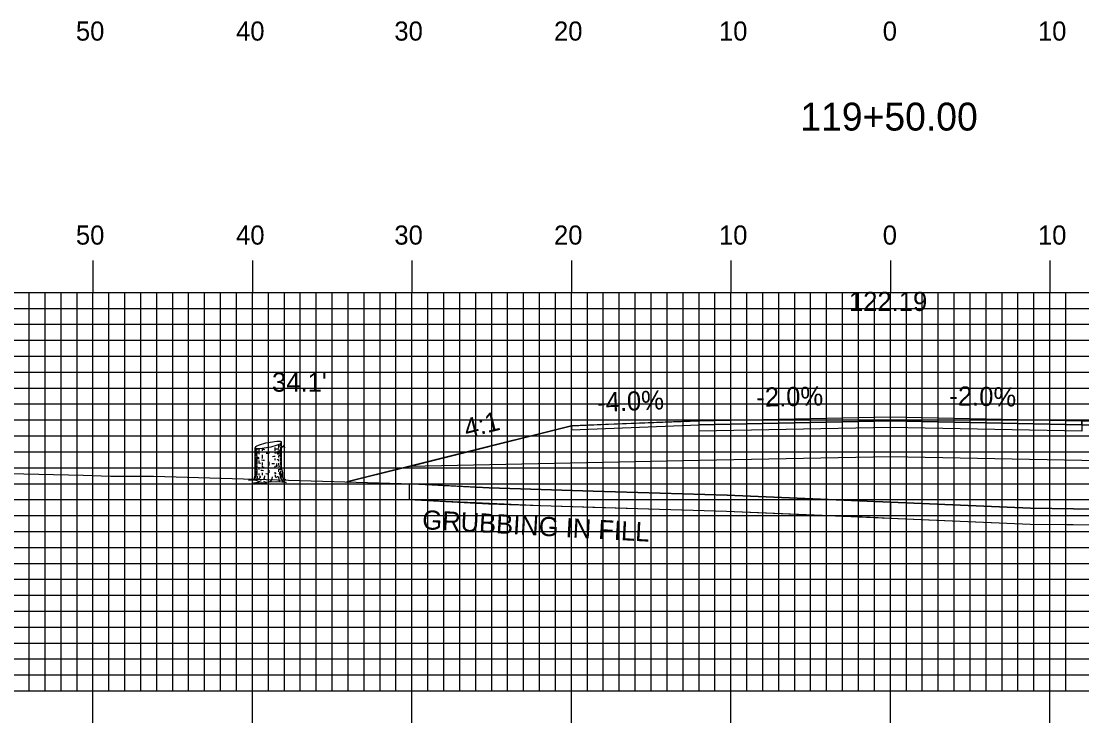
# Model space of a CAD drawing. Extents: x 1771629 to 1771972, y 442591 to 442811.
# Drawn here: x 1771740.1 to 1771806.6, y 442696.7 to 442740.7 of the extents above; entities that cross this region are included whole.
import ezdxf

# ---------------------------------------------------------------- set-up
doc = ezdxf.new("R2010")
doc.units = 0
for name, color, linetype in [('ANNOTATION', 7, 'Continuous'), ('D_Roadway_Centerline', 7, 'Continuous'), ('D_Roadway_Centerline_Text', 7, 'Continuous'), ('D_Roadway_Edge_Shoulder', 7, 'Continuous'), ('D_Roadway_Edge_TW', 7, 'Continuous'), ('D_Roadway_Pavement', 7, 'Continuous'), ('D_Roadway_SlopeLines', 7, 'Continuous'), ('D_Roadway_SubGrade', 7, 'Continuous'), ('D_Text_Standard', 7, 'Continuous'), ('GRUBBING IN FILL', 7, 'Continuous'), ('H_V ANNOTATION', 7, 'Continuous'), ('M_Trees_Conifer_Pay', 7, 'Continuous'), ('MAJOR', 7, 'Continuous'), ('MINOR', 7, 'Continuous'), ('S_Roadway_Centerline', 7, 'Continuous')]:
    doc.layers.add(name, color=color, linetype=linetype)

msp = doc.modelspace()

# ---------------------------------------------------------------- linework, layer by layer
at = {"layer": 'D_Roadway_Centerline'}
msp.add_lwpolyline([(1771760.497, 442711.776), (1771764.04, 442712.662), (1771764.407, 442712.753), (1771767.076, 442713.421), (1771774.552, 442715.29), (1771774.581, 442715.297), (1771776.908, 442715.39), (1771782.58, 442715.617), (1771794.576, 442715.857), (1771794.581, 442715.857), (1771806.579, 442715.617), (1771806.58, 442715.617), (1771809.705, 442715.492), (1771814.547, 442715.299), (1771814.58, 442715.297), (1771824.673, 442712.774), (1771824.754, 442712.753), (1771824.845, 442712.731), (1771834.313, 442710.363), (1771835.958, 442709.952)], dxfattribs=at)
at = {"layer": 'D_Roadway_Edge_Shoulder'}
for points in [[(1771782.58, 442715.617), (1771774.581, 442715.297), (1771774.581, 442715.047), (1771782.58, 442715.367)], [(1771806.58, 442715.617), (1771814.58, 442715.297), (1771814.58, 442715.047), (1771806.58, 442715.367)]]:
    msp.add_lwpolyline(points, close=True, dxfattribs=at)
at = {"layer": 'D_Roadway_Edge_TW'}
msp.add_lwpolyline([(1771782.58, 442715.367), (1771782.58, 442715.617), (1771794.581, 442715.857), (1771806.58, 442715.617), (1771806.58, 442715.367), (1771794.581, 442715.607)], close=True, dxfattribs=at)
at = {"layer": 'D_Roadway_Pavement'}
msp.add_lwpolyline([(1771782.58, 442714.95), (1771782.58, 442715.367), (1771794.581, 442715.607), (1771806.58, 442715.367), (1771806.58, 442714.95), (1771794.581, 442715.19)], close=True, dxfattribs=at)
at = {"layer": 'D_Roadway_SlopeLines'}
msp.add_lwpolyline([(1771774.581, 442715.297), (1771760.497, 442711.776)], dxfattribs=at)
at = {"layer": 'D_Roadway_SubGrade'}
msp.add_lwpolyline([(1771782.58, 442713.117), (1771764.406, 442712.753), (1771774.581, 442715.297), (1771774.581, 442715.047), (1771782.58, 442715.367), (1771794.581, 442715.607), (1771806.58, 442715.367), (1771814.58, 442715.047), (1771814.58, 442715.297), (1771824.754, 442712.753), (1771806.58, 442713.117), (1771794.581, 442713.357)], close=True, dxfattribs=at)
at = {"layer": 'GRUBBING IN FILL'}
msp.add_line((1771764.406, 442711.66), (1771764.406, 442710.663), dxfattribs=at)
msp.add_line((1771764.406, 442711.66), (1771764.406, 442710.663), dxfattribs=at)
for points in [[(1771764.406, 442710.663), (1771772.65, 442710.296), (1771780.107, 442710.064), (1771784.299, 442709.937), (1771793.82, 442709.534), (1771794.58, 442709.502), (1771794.58, 442710.503), (1771784.335, 442710.937), (1771775.947, 442711.189), (1771772.686, 442711.295), (1771769.426, 442711.401), (1771764.406, 442711.66)], [(1771764.406, 442710.663), (1771772.65, 442710.296), (1771780.107, 442710.064), (1771784.299, 442709.937), (1771793.82, 442709.534), (1771794.58, 442709.502), (1771794.58, 442710.503), (1771784.335, 442710.937), (1771775.947, 442711.189), (1771772.686, 442711.295), (1771769.426, 442711.401), (1771764.406, 442711.66)], [(1771794.58, 442709.502), (1771803.34, 442709.131), (1771810.221, 442709.056), (1771814.394, 442709.016), (1771819.574, 442708.992), (1771824.754, 442708.968), (1771824.754, 442709.968), (1771820.08, 442709.99), (1771814.401, 442710.016), (1771806.06, 442710.097), (1771803.368, 442710.131), (1771794.58, 442710.503)], [(1771794.58, 442709.502), (1771803.34, 442709.131), (1771810.221, 442709.056), (1771814.394, 442709.016), (1771819.574, 442708.992), (1771824.754, 442708.968), (1771824.754, 442709.968), (1771820.08, 442709.99), (1771814.401, 442710.016), (1771806.06, 442710.097), (1771803.368, 442710.131), (1771794.58, 442710.503)]]:
    msp.add_lwpolyline(points, close=True, dxfattribs=at)
msp.add_lwpolyline([(1771764.406, 442710.663), (1771769.384, 442710.401), (1771775.916, 442710.19), (1771784.299, 442709.937), (1771803.34, 442709.131), (1771806.049, 442709.097), (1771814.394, 442709.016), (1771824.754, 442708.968)], dxfattribs=at)
msp.add_lwpolyline([(1771764.406, 442710.663), (1771769.384, 442710.401), (1771775.916, 442710.19), (1771784.299, 442709.937), (1771803.34, 442709.131), (1771806.049, 442709.097), (1771814.394, 442709.016), (1771824.754, 442708.968)], dxfattribs=at)
at = {"layer": 'M_Trees_Conifer_Pay'}
for p, q in [((1771756.335, 442714.187), (1771756.335, 442714.025)), ((1771756.407, 442712.612), (1771756.407, 442714.259)), ((1771754.743, 442712.202), (1771754.743, 442713.924)), ((1771754.79, 442713.887), (1771754.79, 442713.416)), ((1771754.848, 442713.876), (1771754.848, 442713.778)), ((1771754.848, 442713.704), (1771754.848, 442713.5)), ((1771754.974, 442713.868), (1771754.974, 442713.635)), ((1771754.974, 442713.595), (1771754.974, 442713.521)), ((1771755.194, 442713.888), (1771755.194, 442713.72)), ((1771755.599, 442713.656), (1771755.599, 442713.561)), ((1771755.99, 442713.93), (1771755.99, 442713.731)), ((1771755.99, 442713.673), (1771755.99, 442713.584)), ((1771756.218, 442714.126), (1771756.218, 442713.903)), ((1771756.218, 442713.815), (1771756.218, 442713.767)), ((1771756.275, 442713.631), (1771756.224, 442713.572)), ((1771756.335, 442713.957), (1771756.335, 442713.829)), ((1771756.335, 442713.642), (1771756.335, 442713.306)), ((1771754.79, 442713.351), (1771754.79, 442713.043)), ((1771754.79, 442712.996), (1771754.79, 442712.504)), ((1771754.848, 442713.442), (1771754.848, 442713.242)), ((1771754.848, 442713.195), (1771754.848, 442712.859)), ((1771754.974, 442713.117), (1771754.974, 442712.979)), ((1771755.194, 442713.483), (1771755.194, 442713.246)), ((1771755.194, 442713.002), (1771755.194, 442712.849)), ((1771755.599, 442713.043), (1771755.599, 442712.969)), ((1771755.599, 442712.944), (1771755.599, 442712.796)), ((1771755.99, 442713.236), (1771755.99, 442713.131)), ((1771756.218, 442713.432), (1771756.218, 442713.3)), ((1771756.218, 442713.189), (1771756.218, 442713.08)), ((1771756.218, 442712.944), (1771756.218, 442712.802)), ((1771756.335, 442713.269), (1771756.335, 442713.107)), ((1771756.335, 442713.059), (1771756.335, 442712.843)), ((1771754.79, 442712.45), (1771754.79, 442712.202)), ((1771754.848, 442712.806), (1771754.848, 442712.67)), ((1771754.848, 442712.571), (1771754.848, 442712.193)), ((1771754.974, 442712.707), (1771754.974, 442712.565)), ((1771754.974, 442712.303), (1771754.974, 442712.209)), ((1771755.194, 442712.806), (1771755.194, 442712.633)), ((1771755.194, 442712.355), (1771755.194, 442712.202)), ((1771755.599, 442712.504), (1771755.599, 442712.351)), ((1771755.99, 442712.765), (1771755.99, 442712.618)), ((1771755.99, 442712.386), (1771755.99, 442712.298)), ((1771756.218, 442712.575), (1771756.218, 442712.402)), ((1771756.335, 442712.812), (1771756.335, 442712.738)), ((1771756.335, 442712.697), (1771756.335, 442712.524)), ((1771754.974, 442711.809), (1771755.137, 442711.873)), ((1771755.411, 442711.745), (1771755.285, 442711.809))]:
    msp.add_line(p, q, dxfattribs=at)
for points in [[(1771756.19, 442713.72), (1771756.159, 442713.635), (1771756.156, 442713.568), (1771756.186, 442713.504)], [(1771756.224, 442713.757), (1771756.261, 442713.683), (1771756.308, 442713.74), (1771756.366, 442713.809), (1771756.458, 442714.002), (1771756.522, 442714.049), (1771756.553, 442714.056)], [(1771756.238, 442713.504), (1771756.275, 442713.631), (1771756.339, 442713.747), (1771756.369, 442713.815), (1771756.438, 442713.961)], [(1771756.453, 442713.99), (1771756.528, 442713.998), (1771756.6, 442713.899)], [(1771754.922, 442713.23), (1771754.916, 442713.325), (1771754.959, 442713.302), (1771754.959, 442713.208)], [(1771756.061, 442712.831), (1771756.074, 442712.754), (1771756.121, 442712.765), (1771756.108, 442712.931)], [(1771756.407, 442712.612), (1771756.458, 442712.351), (1771756.474, 442712.077), (1771756.532, 442711.952), (1771756.668, 442711.921), (1771756.438, 442711.883), (1771756.438, 442711.883), (1771756.444, 442711.836), (1771756.691, 442711.742), (1771756.417, 442711.758), (1771756.061, 442711.778), (1771755.74, 442711.768), (1771755.746, 442711.851), (1771755.598, 442711.768), (1771755.411, 442711.745), (1771755.435, 442711.677), (1771755.167, 442711.721), (1771754.947, 442711.694), (1771754.654, 442711.711), (1771754.943, 442711.768), (1771754.974, 442711.809), (1771754.811, 442711.867), (1771754.574, 442711.878), (1771754.333, 442711.878), (1771754.675, 442711.935), (1771754.717, 442712.015), (1771754.743, 442712.202)], [(1771755.997, 442712.219), (1771756.007, 442712.093), (1771756.081, 442712.05)], [(1771756.234, 442712.324), (1771756.308, 442712.219), (1771756.312, 442712.046), (1771756.438, 442711.883)], [(1771756.333, 442712.47), (1771756.339, 442712.324), (1771756.386, 442712.256), (1771756.396, 442712.057)], [(1771754.791, 442712.155), (1771754.77, 442712.077), (1771754.749, 442711.983)], [(1771754.869, 442712.135), (1771754.875, 442712.019), (1771754.822, 442711.931), (1771754.811, 442711.867)], [(1771755.032, 442712.162), (1771755.032, 442712.03), (1771754.943, 442711.931)], [(1771755.258, 442711.921), (1771755.325, 442712.015), (1771755.352, 442712.155)], [(1771755.746, 442711.851), (1771755.82, 442711.992), (1771755.83, 442712.093)], [(1771756.275, 442711.83), (1771756.261, 442711.968), (1771756.186, 442712.097)]]:
    msp.add_lwpolyline(points, dxfattribs=at)
for centre, radius, start, end in [((1771756.599, 442709.157), 5.179, 101.7194, 108.05939), ((1771756.599, 442709.157), 5.179, 95.37941, 101.7194), ((1771756.188, 442713.515), 0.802, 79.2194, 95.37941), ((1771755.908, 442714.865), 0.802, 288.05939, 304.2194), ((1771756.291, 442714.056), 0.251, 71.05013, 79.2194), ((1771756.218, 442714.41), 0.251, 304.2194, 312.38868), ((1771756.346, 442714.216), 0.0817, 56.7194, 71.05013), ((1771756.332, 442714.285), 0.0817, 312.38868, 326.7194), ((1771756.362, 442714.24), 0.0527, 46.92298, 56.7194), ((1771756.377, 442714.255), 0.0314, 34.2194, 46.92298), ((1771756.356, 442714.269), 0.0527, 326.7194, 336.51582), ((1771756.381, 442714.258), 0.0264, 23.40735, 34.2194), ((1771756.376, 442714.261), 0.0314, 336.51582, 349.2194), ((1771756.384, 442714.26), 0.0226, 11.7194, 23.40735), ((1771756.384, 442714.26), 0.0226, 0.03145, 11.7194), ((1771756.381, 442714.26), 0.0264, 349.2194, 0.03145), ((1771754.775, 442713.746), 0.0334, 163.94846, 180), ((1771754.775, 442713.746), 0.0334, 180, 196.05154), ((1771754.774, 442713.923), 0.0314, 156.51582, 169.2194), ((1771754.769, 442713.924), 0.0264, 169.2194, 180.03145), ((1771754.766, 442713.924), 0.0226, 180.03145, 191.7194), ((1771754.766, 442713.924), 0.0226, 191.7194, 203.40735), ((1771754.785, 442713.749), 0.0441, 196.05154, 210), ((1771754.794, 442713.914), 0.0527, 146.7194, 156.51582), ((1771754.769, 442713.925), 0.0264, 203.40735, 214.2194), ((1771754.773, 442713.928), 0.0314, 214.2194, 226.92298), ((1771754.801, 442713.758), 0.0624, 210, 228.74941), ((1771754.818, 442713.899), 0.0817, 132.38868, 146.7194), ((1771754.788, 442713.944), 0.0527, 226.92298, 236.7194), ((1771754.804, 442713.968), 0.0817, 236.7194, 251.05013), ((1771754.874, 442713.841), 0.172, 228.74941, 240), ((1771754.932, 442713.774), 0.251, 124.2194, 132.38868), ((1771754.858, 442714.128), 0.251, 251.05013, 259.2194), ((1771755.073, 442714.186), 0.571, 240, 240.33672), ((1771755.242, 442713.318), 0.802, 108.05939, 124.2194), ((1771754.962, 442714.669), 0.802, 259.2194, 275.37941), ((1771755.073, 442714.186), 0.571, 246.85973, 257.98457), ((1771754.551, 442719.027), 5.179, 275.37941, 281.7194), ((1771755.575, 442717.936), 4.124, 264.6955, 266.73309), ((1771755.574, 442717.703), 4.124, 268.07512, 270), ((1771755.574, 442717.703), 4.124, 270, 270.35814), ((1771754.551, 442719.027), 5.179, 281.7194, 288.05939), ((1771755.574, 442717.703), 4.124, 275.78493, 277.05584), ((1771755.575, 442717.936), 4.124, 276.23804, 278.1032), ((1771756.076, 442714.419), 0.571, 278.1032, 284.36665), ((1771756.076, 442714.573), 0.571, 284.43166, 292.41325), ((1771756.076, 442714.419), 0.571, 297.0237, 300), ((1771756.275, 442714.228), 0.172, 300, 311.25059), ((1771756.275, 442714.073), 0.172, 300, 311.25059), ((1771756.348, 442714.145), 0.0624, 311.25059, 330), ((1771756.348, 442713.991), 0.0624, 311.25059, 330), ((1771756.363, 442714.136), 0.0441, 330, 343.94846), ((1771756.363, 442713.982), 0.0441, 330, 343.94846), ((1771756.374, 442714.133), 0.0334, 343.94846, 354.21506), ((1771756.374, 442713.979), 0.0334, 343.94846, 354.21506), ((1771756.374, 442713.535), 0.0334, 343.94846, 354.21506), ((1771754.775, 442713.299), 0.0334, 163.94846, 180), ((1771754.775, 442713.299), 0.0334, 180, 196.05154), ((1771754.775, 442713.089), 0.0334, 163.94846, 180), ((1771754.775, 442713.089), 0.0334, 180, 196.05154), ((1771754.775, 442712.852), 0.0334, 163.94846, 180), ((1771754.775, 442712.852), 0.0334, 180, 196.05154), ((1771754.785, 442713.302), 0.0441, 196.05154, 210), ((1771754.785, 442713.092), 0.0441, 196.05154, 210), ((1771754.801, 442713.311), 0.0624, 210, 228.74941), ((1771754.801, 442713.101), 0.0624, 210, 228.74941), ((1771754.874, 442713.394), 0.172, 228.74941, 240), ((1771754.874, 442713.184), 0.172, 228.74941, 240), ((1771755.073, 442713.739), 0.571, 240, 240.33672), ((1771755.073, 442713.529), 0.571, 240, 246.85973), ((1771755.074, 442713.975), 0.571, 240, 247.05866), ((1771755.073, 442713.529), 0.571, 259.27072, 261.8968), ((1771755.574, 442717.046), 4.124, 261.8968, 263.14738), ((1771755.574, 442717.256), 4.124, 264.08098, 266.66759), ((1771755.574, 442717.046), 4.124, 270, 270.35814), ((1771755.574, 442717.046), 4.124, 273.14934, 275.45691), ((1771755.575, 442717.492), 4.124, 273.70524, 275.95043), ((1771755.574, 442717.256), 4.124, 277.61247, 278.1032), ((1771756.074, 442713.739), 0.571, 278.1032, 286.92962), ((1771756.076, 442713.975), 0.571, 284.44928, 297.04285), ((1771756.074, 442713.739), 0.571, 297.18959, 300), ((1771756.074, 442713.529), 0.571, 297.18959, 300), ((1771756.274, 442713.394), 0.172, 300, 311.25059), ((1771756.274, 442713.184), 0.172, 300, 311.25059), ((1771756.346, 442713.311), 0.0624, 311.25059, 330), ((1771756.346, 442713.101), 0.0624, 311.25059, 330), ((1771756.362, 442713.302), 0.0441, 330, 343.94846), ((1771756.362, 442713.092), 0.0441, 330, 343.94846), ((1771756.372, 442713.299), 0.0334, 343.94846, 354.21506), ((1771756.372, 442713.089), 0.0334, 343.94846, 354.21506), ((1771754.775, 442712.655), 0.0334, 163.94846, 180), ((1771754.775, 442712.459), 0.0334, 163.94846, 180), ((1771754.775, 442712.459), 0.0334, 180, 196.05154), ((1771754.775, 442712.239), 0.0334, 163.94846, 180), ((1771754.775, 442712.239), 0.0334, 180, 196.05154), ((1771754.785, 442712.855), 0.0441, 196.05154, 210), ((1771754.785, 442712.462), 0.0441, 196.05154, 210), ((1771754.785, 442712.242), 0.0441, 196.05154, 210), ((1771754.801, 442712.864), 0.0624, 210, 228.74941), ((1771754.801, 442712.471), 0.0624, 210, 228.74941), ((1771754.801, 442712.251), 0.0624, 210, 228.74941), ((1771754.874, 442712.947), 0.172, 228.74941, 240), ((1771754.874, 442712.554), 0.172, 228.74941, 240), ((1771754.874, 442712.333), 0.172, 228.74941, 240), ((1771755.073, 442713.292), 0.571, 240, 246.85973), ((1771755.062, 442713.1), 0.571, 241.23686, 248.02677), ((1771755.073, 442712.899), 0.571, 240, 246.85973), ((1771755.073, 442712.678), 0.571, 240, 244.53138), ((1771755.574, 442716.612), 4.124, 263.49906, 265.83975), ((1771755.574, 442716.81), 4.124, 264.71603, 266.31934), ((1771755.574, 442716.416), 4.124, 267.81166, 270), ((1771755.574, 442716.416), 4.124, 270, 270.13279), ((1771755.574, 442716.416), 4.124, 275.78493, 276.78961), ((1771756.074, 442713.292), 0.571, 285.39827, 297.18959), ((1771756.074, 442712.899), 0.571, 288.50673, 297.27208), ((1771756.074, 442713.094), 0.571, 289.29072, 300), ((1771756.274, 442712.749), 0.172, 300, 311.25059), ((1771756.274, 442712.333), 0.172, 300, 311.25059), ((1771756.346, 442712.667), 0.0624, 311.25059, 330), ((1771756.346, 442712.251), 0.0624, 311.25059, 330), ((1771756.362, 442712.658), 0.0441, 330, 343.94846), ((1771756.362, 442712.242), 0.0441, 330, 343.94846), ((1771756.372, 442712.655), 0.0334, 343.94846, 354.21506), ((1771756.372, 442712.239), 0.0334, 343.94846, 354.21506), ((1771755.574, 442716.196), 4.124, 262.44379, 263.51202), ((1771755.574, 442716.196), 4.124, 277.36842, 278.1032), ((1771756.074, 442712.678), 0.571, 278.1032, 281.63703)]:
    msp.add_arc(centre, radius, start, end, dxfattribs=at)
at = {"layer": 'MAJOR'}
for p, q in [((1771744.58, 442725.669), (1771744.58, 442723.665)), ((1771754.58, 442725.669), (1771754.58, 442723.665)), ((1771764.58, 442725.669), (1771764.58, 442723.665)), ((1771774.58, 442725.669), (1771774.58, 442723.665)), ((1771784.58, 442725.669), (1771784.58, 442723.665)), ((1771794.58, 442725.669), (1771794.58, 442723.665)), ((1771804.58, 442725.669), (1771804.58, 442723.665)), ((1771654.58, 442723.665), (1771934.58, 442723.665)), ((1771654.58, 442723.665), (1771934.58, 442723.665)), ((1771744.58, 442698.665), (1771744.58, 442723.665)), ((1771754.58, 442698.665), (1771754.58, 442723.665)), ((1771764.58, 442698.665), (1771764.58, 442723.665)), ((1771774.58, 442698.665), (1771774.58, 442723.665)), ((1771784.58, 442698.665), (1771784.58, 442723.665)), ((1771794.58, 442698.665), (1771794.58, 442723.665)), ((1771804.58, 442698.665), (1771804.58, 442723.665)), ((1771654.58, 442718.665), (1771934.58, 442718.665)), ((1771654.58, 442713.665), (1771934.58, 442713.665)), ((1771654.58, 442708.665), (1771934.58, 442708.665)), ((1771654.58, 442703.665), (1771934.58, 442703.665)), ((1771654.58, 442698.665), (1771934.58, 442698.665)), ((1771654.58, 442698.665), (1771934.58, 442698.665)), ((1771744.58, 442696.661), (1771744.58, 442698.665)), ((1771754.58, 442696.661), (1771754.58, 442698.665)), ((1771764.58, 442696.661), (1771764.58, 442698.665)), ((1771774.58, 442696.661), (1771774.58, 442698.665)), ((1771784.58, 442696.661), (1771784.58, 442698.665)), ((1771794.58, 442696.661), (1771794.58, 442698.665)), ((1771804.58, 442696.661), (1771804.58, 442698.665))]:
    msp.add_line(p, q, dxfattribs=at)
at = {"layer": 'MINOR'}
for p, q in [((1771740.58, 442698.665), (1771740.58, 442723.665)), ((1771741.58, 442698.665), (1771741.58, 442723.665)), ((1771742.58, 442698.665), (1771742.58, 442723.665)), ((1771743.58, 442698.665), (1771743.58, 442723.665)), ((1771745.58, 442698.665), (1771745.58, 442723.665)), ((1771746.58, 442698.665), (1771746.58, 442723.665)), ((1771747.58, 442698.665), (1771747.58, 442723.665)), ((1771748.58, 442698.665), (1771748.58, 442723.665)), ((1771749.58, 442698.665), (1771749.58, 442723.665)), ((1771750.58, 442698.665), (1771750.58, 442723.665)), ((1771751.58, 442698.665), (1771751.58, 442723.665)), ((1771752.58, 442698.665), (1771752.58, 442723.665)), ((1771753.58, 442698.665), (1771753.58, 442723.665)), ((1771755.58, 442698.665), (1771755.58, 442723.665)), ((1771756.58, 442698.665), (1771756.58, 442723.665)), ((1771757.58, 442698.665), (1771757.58, 442723.665)), ((1771758.58, 442698.665), (1771758.58, 442723.665)), ((1771759.58, 442698.665), (1771759.58, 442723.665)), ((1771760.58, 442698.665), (1771760.58, 442723.665)), ((1771761.58, 442698.665), (1771761.58, 442723.665)), ((1771762.58, 442698.665), (1771762.58, 442723.665)), ((1771763.58, 442698.665), (1771763.58, 442723.665)), ((1771765.58, 442698.665), (1771765.58, 442723.665)), ((1771766.58, 442698.665), (1771766.58, 442723.665)), ((1771767.58, 442698.665), (1771767.58, 442723.665)), ((1771768.58, 442698.665), (1771768.58, 442723.665)), ((1771769.58, 442698.665), (1771769.58, 442723.665)), ((1771770.58, 442698.665), (1771770.58, 442723.665)), ((1771771.58, 442698.665), (1771771.58, 442723.665)), ((1771772.58, 442698.665), (1771772.58, 442723.665)), ((1771773.58, 442698.665), (1771773.58, 442723.665)), ((1771775.58, 442698.665), (1771775.58, 442723.665)), ((1771776.58, 442698.665), (1771776.58, 442723.665)), ((1771777.58, 442698.665), (1771777.58, 442723.665)), ((1771778.58, 442698.665), (1771778.58, 442723.665)), ((1771779.58, 442698.665), (1771779.58, 442723.665)), ((1771780.58, 442698.665), (1771780.58, 442723.665)), ((1771781.58, 442698.665), (1771781.58, 442723.665)), ((1771782.58, 442698.665), (1771782.58, 442723.665)), ((1771783.58, 442698.665), (1771783.58, 442723.665)), ((1771785.58, 442698.665), (1771785.58, 442723.665)), ((1771786.58, 442698.665), (1771786.58, 442723.665)), ((1771787.58, 442698.665), (1771787.58, 442723.665)), ((1771788.58, 442698.665), (1771788.58, 442723.665)), ((1771789.58, 442698.665), (1771789.58, 442723.665)), ((1771790.58, 442698.665), (1771790.58, 442723.665)), ((1771791.58, 442698.665), (1771791.58, 442723.665)), ((1771792.58, 442698.665), (1771792.58, 442723.665)), ((1771793.58, 442698.665), (1771793.58, 442723.665)), ((1771795.58, 442698.665), (1771795.58, 442723.665)), ((1771796.58, 442698.665), (1771796.58, 442723.665)), ((1771797.58, 442698.665), (1771797.58, 442723.665)), ((1771798.58, 442698.665), (1771798.58, 442723.665)), ((1771799.58, 442698.665), (1771799.58, 442723.665)), ((1771800.58, 442698.665), (1771800.58, 442723.665)), ((1771801.58, 442698.665), (1771801.58, 442723.665)), ((1771802.58, 442698.665), (1771802.58, 442723.665)), ((1771803.58, 442698.665), (1771803.58, 442723.665)), ((1771805.58, 442698.665), (1771805.58, 442723.665)), ((1771654.58, 442722.665), (1771934.58, 442722.665)), ((1771654.58, 442721.665), (1771934.58, 442721.665)), ((1771654.58, 442720.665), (1771934.58, 442720.665)), ((1771654.58, 442719.665), (1771934.58, 442719.665)), ((1771654.58, 442717.665), (1771934.58, 442717.665)), ((1771654.58, 442716.665), (1771934.58, 442716.665)), ((1771654.58, 442715.665), (1771934.58, 442715.665)), ((1771654.58, 442714.665), (1771934.58, 442714.665)), ((1771654.58, 442712.665), (1771934.58, 442712.665)), ((1771654.58, 442711.665), (1771934.58, 442711.665)), ((1771654.58, 442710.665), (1771934.58, 442710.665)), ((1771654.58, 442709.665), (1771934.58, 442709.665)), ((1771654.58, 442707.665), (1771934.58, 442707.665)), ((1771654.58, 442706.665), (1771934.58, 442706.665)), ((1771654.58, 442705.665), (1771934.58, 442705.665)), ((1771654.58, 442704.665), (1771934.58, 442704.665)), ((1771654.58, 442702.665), (1771934.58, 442702.665)), ((1771654.58, 442701.665), (1771934.58, 442701.665)), ((1771654.58, 442700.665), (1771934.58, 442700.665)), ((1771654.58, 442699.665), (1771934.58, 442699.665))]:
    msp.add_line(p, q, dxfattribs=at)
at = {"layer": 'S_Roadway_Centerline'}
msp.add_lwpolyline([(1771734.669, 442712.402), (1771743.955, 442712.204), (1771745.693, 442712.138), (1771748.383, 442712.136), (1771764.62, 442711.653), (1771769.426, 442711.401), (1771775.947, 442711.189), (1771784.335, 442710.937), (1771803.368, 442710.131), (1771806.06, 442710.097), (1771814.401, 442710.016), (1771825.759, 442709.964), (1771827.662, 442709.962), (1771830.368, 442709.98), (1771837.415, 442709.945), (1771846.068, 442709.775), (1771859.884, 442709)], dxfattribs=at)

# ---------------------------------------------------------------- texts
at = {"layer": 'ANNOTATION'}
for s, rotation, p in [('-4.0%', 2.29073, (1771776.212, 442716.164)), ('-2.0%', 1.14573, (1771786.184, 442716.49)), ('-2.0%', 358.8542, (1771798.266, 442716.584)), ('4:1', 14.03877, (1771768.015, 442714.517))]:
    msp.add_text(s, height=1.2, rotation=rotation, dxfattribs=at).set_placement(p)
at = {"layer": 'D_Roadway_Centerline'}
for s, p in [('C', (1771794.575, 442715.857)), ('L', (1771794.581, 442715.85))]:
    msp.add_text(s, height=0.0146, dxfattribs=at).set_placement(p)
at = {"layer": 'D_Roadway_Centerline_Text'}
msp.add_text('122.19', height=1.2, dxfattribs=at).set_placement((1771791.982, 442722.501))
at = {"layer": 'D_Text_Standard'}
msp.add_text("34.1'", height=1.2, dxfattribs=at).set_placement((1771755.808, 442717.437))
at = {"layer": 'GRUBBING IN FILL'}
msp.add_text('GRUBBING IN FILL', height=1.2, rotation=356.82289, dxfattribs=at).set_placement((1771765.2, 442708.815))
at = {"layer": 'H_V ANNOTATION'}
for s, height, p in [('50', 1.2, (1771743.51, 442739.465)), ('40', 1.2, (1771753.553, 442739.465)), ('30', 1.2, (1771763.478, 442739.465)), ('20', 1.2, (1771773.488, 442739.465)), ('10', 1.2, (1771783.831, 442739.465)), ('0', 1.2, (1771794.099, 442739.465)), ('10', 1.2, (1771803.831, 442739.465)), ('119+50.00', 1.75, (1771788.931, 442733.821)), ('50', 1.2, (1771743.51, 442726.665)), ('40', 1.2, (1771753.553, 442726.665)), ('30', 1.2, (1771763.478, 442726.665)), ('20', 1.2, (1771773.488, 442726.665)), ('10', 1.2, (1771783.831, 442726.665)), ('0', 1.2, (1771794.099, 442726.665)), ('10', 1.2, (1771803.831, 442726.665))]:
    msp.add_text(s, height=height, dxfattribs=at).set_placement(p)

doc.saveas('drawing.dxf')
